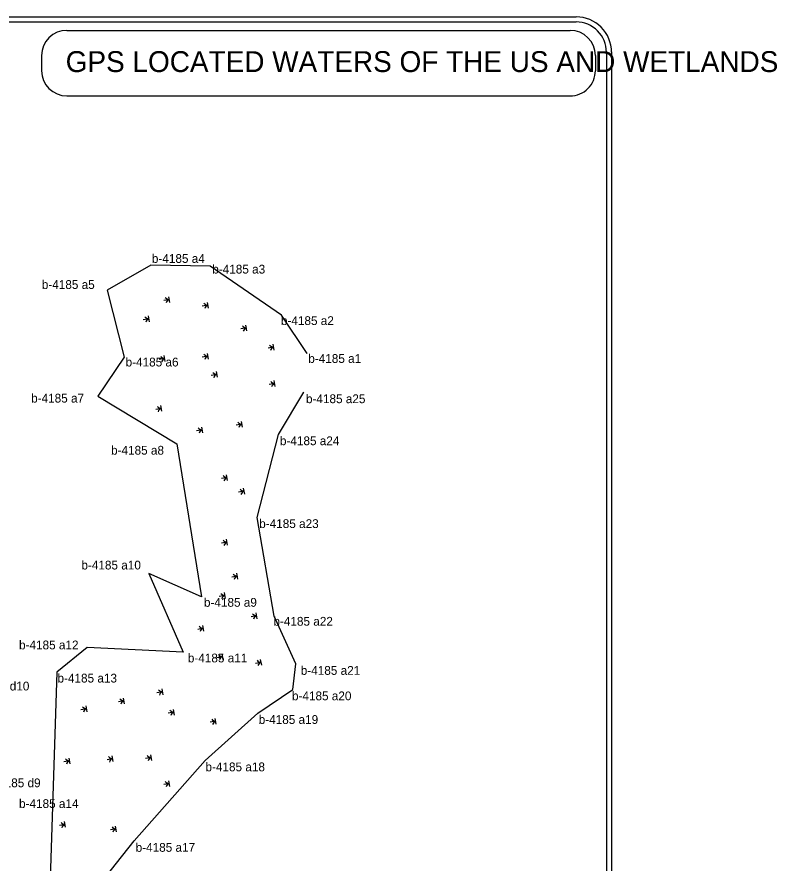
# Model space of a CAD drawing. Extents: x 2598976 to 2600165, y 728604 to 730243.
# Drawn here: x 2599517 to 2600165, y 729516 to 730238 of the extents above; entities that cross this region are included whole.
import ezdxf

# ---------------------------------------------------------------- set-up
doc = ezdxf.new("R2010")
doc.units = 0
for name, color, linetype in [('Old_Level_24', 7, 'Continuous'), ('Old_Level_3', 7, 'Continuous'), ('Old_Level_57', 7, 'Continuous'), ('Old_Level_63', 7, 'Continuous')]:
    doc.layers.add(name, color=color, linetype=linetype)

msp = doc.modelspace()

# ---------------------------------------------------------------- linework, layer by layer
at = {"layer": 'Old_Level_3'}
for p, q in [((2599631.03, 730026.43), (2599631.03, 730026.43)), ((2599681.7, 730025.47), (2599681.7, 730025.47)), ((2599593.82, 730004.86), (2599593.82, 730004.86)), ((2599742.64, 729983.6), (2599742.64, 729983.6)), ((2599764.34, 729950.8), (2599764.34, 729950.8)), ((2599608.29, 729947.7), (2599608.29, 729947.7)), ((2599585.75, 729914.54), (2599585.75, 729914.54)), ((2599761.65, 729918), (2599761.65, 729918)), ((2599739.87, 729881.74), (2599739.87, 729881.74)), ((2599653.16, 729873.76), (2599653.16, 729873.76)), ((2599721.7, 729811.02), (2599721.7, 729811.02)), ((2599629.44, 729763.19), (2599629.44, 729763.19)), ((2599674.31, 729743.3), (2599674.31, 729743.3)), ((2599736.31, 729726.61), (2599736.31, 729726.61)), ((2599576.74, 729699.88), (2599576.74, 729699.88)), ((2599658.53, 729696.04), (2599658.53, 729696.04)), ((2599754.67, 729686.08), (2599754.67, 729686.08)), ((2599550.79, 729678.88), (2599550.79, 729678.88)), ((2599752.22, 729664.15), (2599752.22, 729664.15)), ((2599722.5, 729643.95), (2599722.5, 729643.95)), ((2599677.31, 729603.47), (2599677.31, 729603.47)), ((2599616.95, 729534.95), (2599616.95, 729534.95))]:
    msp.add_line(p, q, dxfattribs=at)
at = {"layer": 'Old_Level_57'}
for p, q in [((2599646.85, 729996.92), (2599642.05, 729996.07)), ((2599647.28, 729994.46), (2599646.41, 729999.38)), ((2599680.17, 729989.62), (2599679.3, 729994.54)), ((2599679.73, 729992.08), (2599674.94, 729991.23)), ((2599629.43, 729980.47), (2599624.64, 729979.61)), ((2599629.87, 729978.01), (2599628.99, 729982.93)), ((2599712.62, 729972.73), (2599707.83, 729971.87)), ((2599713.06, 729970.26), (2599712.19, 729975.19)), ((2599736.28, 729953.81), (2599735.4, 729958.74)), ((2599680.17, 729946.07), (2599679.3, 729950.99)), ((2599735.84, 729956.27), (2599731.05, 729955.42)), ((2599642.98, 729946.6), (2599638.19, 729945.74)), ((2599643.41, 729944.14), (2599642.54, 729949.06)), ((2599679.73, 729948.53), (2599674.94, 729947.68)), ((2599687.91, 729930.59), (2599687.03, 729935.51)), ((2599687.47, 729933.05), (2599682.68, 729932.2)), ((2599736.81, 729925.31), (2599732.02, 729924.45)), ((2599737.24, 729922.85), (2599736.37, 729927.77)), ((2599640.51, 729901.56), (2599639.64, 729906.48)), ((2599640.07, 729904.02), (2599635.28, 729903.16)), ((2599709.19, 729888.01), (2599708.32, 729892.93)), ((2599674.9, 729885.63), (2599670.11, 729884.78)), ((2599675.34, 729883.17), (2599674.46, 729888.09)), ((2599708.75, 729890.47), (2599703.96, 729889.62)), ((2599696.18, 729844.98), (2599691.39, 729844.13)), ((2599696.62, 729842.52), (2599695.74, 729847.45)), ((2599711.13, 729830.91), (2599710.25, 729835.83)), ((2599710.69, 729833.37), (2599705.9, 729832.52)), ((2599696.62, 729787.36), (2599695.74, 729792.28)), ((2599696.18, 729789.82), (2599691.39, 729788.97)), ((2599705.32, 729758.33), (2599704.45, 729763.25)), ((2599704.88, 729760.79), (2599700.09, 729759.94)), ((2599694.24, 729744.34), (2599689.45, 729743.49)), ((2599694.68, 729741.88), (2599693.81, 729746.8)), ((2599721.33, 729726.92), (2599716.54, 729726.07)), ((2599721.77, 729724.46), (2599720.89, 729729.38)), ((2599676.3, 729713.81), (2599675.43, 729718.74)), ((2599675.86, 729716.28), (2599671.07, 729715.42)), ((2599692.31, 729692.08), (2599687.52, 729691.23)), ((2599692.75, 729689.62), (2599691.87, 729694.54)), ((2599725.64, 729684.78), (2599724.76, 729689.7)), ((2599725.2, 729687.24), (2599720.41, 729686.39)), ((2599641.04, 729662.08), (2599636.25, 729661.23)), ((2599641.48, 729659.62), (2599640.6, 729664.54)), ((2599608.15, 729654.34), (2599603.36, 729653.49)), ((2599608.59, 729651.88), (2599607.71, 729656.8)), ((2599576.23, 729647.57), (2599571.44, 729646.71)), ((2599576.67, 729645.1), (2599575.79, 729650.03)), ((2599651.15, 729642.2), (2599650.28, 729647.12)), ((2599650.71, 729644.66), (2599645.92, 729643.81)), ((2599686.94, 729634.46), (2599686.07, 729639.38)), ((2599686.51, 729636.92), (2599681.71, 729636.07)), ((2599561.72, 729603.05), (2599556.93, 729602.2)), ((2599562.16, 729600.59), (2599561.28, 729605.51)), ((2599598.48, 729604.99), (2599593.69, 729604.13)), ((2599598.92, 729602.52), (2599598.04, 729607.45)), ((2599631.37, 729605.95), (2599626.58, 729605.1)), ((2599631.81, 729603.49), (2599630.93, 729608.41)), ((2599646.85, 729583.7), (2599642.05, 729582.84)), ((2599647.28, 729581.23), (2599646.41, 729586.16)), ((2599557.85, 729548.86), (2599553.06, 729548)), ((2599558.29, 729546.4), (2599557.41, 729551.32)), ((2599601.82, 729542.52), (2599600.94, 729547.45)), ((2599601.38, 729544.99), (2599596.59, 729544.13))]:
    msp.add_line(p, q, dxfattribs=at)
msp.add_lwpolyline([(2599764.34, 729950.8), (2599742.64, 729983.6), (2599681.7, 730025.47), (2599631.03, 730026.43), (2599593.82, 730004.86), (2599608.29, 729947.7), (2599585.75, 729914.54), (2599653.16, 729873.76), (2599674.31, 729743.3), (2599629.44, 729763.19), (2599658.53, 729696.04), (2599576.74, 729699.88), (2599550.79, 729678.88), (2599545.29, 729502.48), (2599562.01, 729465.34), (2599616.95, 729534.95), (2599677.31, 729603.47), (2599722.5, 729643.95), (2599752.22, 729664.15), (2599754.67, 729686.08), (2599736.31, 729726.61), (2599721.7, 729811.02), (2599739.87, 729881.74), (2599761.65, 729918)], dxfattribs=at)
for centre, radius, start, end in [((2599647.31, 730002.05), 5.15, 220.90031, 264.24799), ((2599647.89, 729993.17), 3.87, 105.65345, 165.99432), ((2599680.2, 729997.22), 5.15, 220.90031, 264.24799), ((2599680.78, 729988.33), 3.87, 105.65345, 165.99432), ((2599629.9, 729985.6), 5.15, 220.90031, 264.24799), ((2599630.48, 729976.72), 3.87, 105.65345, 165.99432), ((2599713.09, 729977.86), 5.15, 220.90031, 264.24799), ((2599713.67, 729968.97), 3.87, 105.65345, 165.99432), ((2599736.31, 729961.41), 5.15, 220.90031, 264.24799), ((2599680.2, 729953.67), 5.15, 220.90031, 264.24799), ((2599736.89, 729952.52), 3.87, 105.65345, 165.99432), ((2599643.44, 729951.73), 5.15, 220.90031, 264.24799), ((2599644.02, 729942.85), 3.87, 105.65345, 165.99432), ((2599680.78, 729944.78), 3.87, 105.65345, 165.99432), ((2599687.94, 729938.18), 5.15, 220.90031, 264.24799), ((2599688.52, 729929.3), 3.87, 105.65345, 165.99432), ((2599737.27, 729930.44), 5.15, 220.90031, 264.24799), ((2599737.85, 729921.55), 3.87, 105.65345, 165.99432), ((2599640.54, 729909.15), 5.15, 220.90031, 264.24799), ((2599641.12, 729900.26), 3.87, 105.65345, 165.99432), ((2599709.22, 729895.6), 5.15, 220.90031, 264.24799), ((2599675.36, 729890.76), 5.15, 220.90031, 264.24799), ((2599675.95, 729881.88), 3.87, 105.65345, 165.99432), ((2599709.8, 729886.72), 3.87, 105.65345, 165.99432), ((2599696.65, 729850.12), 5.15, 220.90031, 264.24799), ((2599697.23, 729841.23), 3.87, 105.65345, 165.99432), ((2599711.16, 729838.51), 5.15, 220.90031, 264.24799), ((2599711.74, 729829.62), 3.87, 105.65345, 165.99432), ((2599696.65, 729794.96), 5.15, 220.90031, 264.24799), ((2599697.23, 729786.07), 3.87, 105.65345, 165.99432), ((2599705.35, 729765.93), 5.15, 220.90031, 264.24799), ((2599705.93, 729757.04), 3.87, 105.65345, 165.99432), ((2599694.71, 729749.47), 5.15, 220.90031, 264.24799), ((2599695.29, 729740.59), 3.87, 105.65345, 165.99432), ((2599721.8, 729732.05), 5.15, 220.90031, 264.24799), ((2599722.38, 729723.17), 3.87, 105.65345, 165.99432), ((2599676.33, 729721.41), 5.15, 220.90031, 264.24799), ((2599676.91, 729712.52), 3.87, 105.65345, 165.99432), ((2599692.78, 729697.22), 5.15, 220.90031, 264.24799), ((2599693.36, 729688.33), 3.87, 105.65345, 165.99432), ((2599725.67, 729692.38), 5.15, 220.90031, 264.24799), ((2599726.25, 729683.49), 3.87, 105.65345, 165.99432), ((2599641.51, 729667.22), 5.15, 220.90031, 264.24799), ((2599642.09, 729658.33), 3.87, 105.65345, 165.99432), ((2599608.62, 729659.47), 5.15, 220.90031, 264.24799), ((2599609.2, 729650.59), 3.87, 105.65345, 165.99432), ((2599576.7, 729652.7), 5.15, 220.90031, 264.24799), ((2599577.28, 729643.81), 3.87, 105.65345, 165.99432), ((2599651.18, 729649.8), 5.15, 220.90031, 264.24799), ((2599651.76, 729640.91), 3.87, 105.65345, 165.99432), ((2599686.97, 729642.06), 5.15, 220.90031, 264.24799), ((2599687.55, 729633.17), 3.87, 105.65345, 165.99432), ((2599562.19, 729608.18), 5.15, 220.90031, 264.24799), ((2599562.77, 729599.3), 3.87, 105.65345, 165.99432), ((2599598.95, 729610.12), 5.15, 220.90031, 264.24799), ((2599599.53, 729601.23), 3.87, 105.65345, 165.99432), ((2599631.83, 729611.09), 5.15, 220.90031, 264.24799), ((2599632.42, 729602.2), 3.87, 105.65345, 165.99432), ((2599647.31, 729588.83), 5.15, 220.90031, 264.24799), ((2599647.89, 729579.94), 3.87, 105.65345, 165.99432), ((2599558.32, 729553.99), 5.15, 220.90031, 264.24799), ((2599558.9, 729545.1), 3.87, 105.65345, 165.99432), ((2599601.85, 729550.12), 5.15, 220.90031, 264.24799), ((2599602.43, 729541.23), 3.87, 105.65345, 165.99432)]:
    msp.add_arc(centre, radius, start, end, dxfattribs=at)
at = {"layer": 'Old_Level_63'}
for p, q in [((2599010.7, 730238.21), (2599994, 730238.21)), ((2599010.7, 730238.21), (2599994, 730238.21)), ((2599010.7, 730238.21), (2599994, 730238.21)), ((2599011, 730233.91), (2599994, 730233.91)), ((2599011, 730233.91), (2599994, 730233.91)), ((2599011, 730233.91), (2599994, 730233.91)), ((2599559.38, 730226.75), (2599988.85, 730226.75)), ((2599537.87, 730205.24), (2599537.87, 730192.28)), ((2600010.36, 730205.24), (2600010.36, 730192.31)), ((2600019.84, 730208.54), (2600019.84, 728674.58)), ((2600019.84, 730208.54), (2600019.84, 728674.58)), ((2600019.84, 730208.54), (2600019.84, 728674.58)), ((2600024.14, 730208.54), (2600024.14, 728674.53)), ((2600024.14, 730208.54), (2600024.14, 728674.53)), ((2600024.14, 730208.54), (2600024.14, 728674.53)), ((2599559.38, 730170.78), (2599988.85, 730170.78))]:
    msp.add_line(p, q, dxfattribs=at)
for centre, major_axis, ratio, start_param, end_param in [((2599994, 730208.07), (-30.14, 0), 0.999993, 3.141591, 4.712389), ((2599994, 730208.07), (-30.14, 0), 0.999993, 3.141591, 4.712389), ((2599994, 730208.07), (-30.14, 0), 0.999993, 3.141591, 4.712389), ((2599994, 730208.07), (-25.83, 0), 0.999998, 3.141591, 4.712389), ((2599994, 730208.07), (-25.83, 0), 0.999998, 3.141591, 4.712389), ((2599994, 730208.07), (-25.83, 0), 0.999998, 3.141591, 4.712389), ((2599559.38, 730205.24), (0, -21.51), 0.999998, 3.141593, 4.712389), ((2599988.85, 730205.24), (0, 21.51), 0.999998, 4.712389, 6.283185), ((2599559.38, 730192.28), (0, -21.51), 0.999998, 4.712389, 6.283185), ((2599988.83, 730192.31), (0, 21.53), 0.999998, 3.141591, 4.712389)]:
    msp.add_ellipse(centre, major_axis=major_axis, ratio=ratio, start_param=start_param, end_param=end_param, dxfattribs=at)

# ---------------------------------------------------------------- texts
at = {"layer": 'Old_Level_24'}
for s, p in [('b-4185 a4', (2599631.96, 730028.23)), ('b-4185 a3', (2599683.47, 730019.14)), ('b-4185 a5', (2599538.03, 730006)), ('b-4185 a2', (2599742.05, 729975.18)), ('b-4185 a1', (2599765.39, 729942.85)), ('b-4185 a6', (2599609.54, 729939.82)), ('b-4185 a7', (2599528.94, 729909)), ('b-4185 a25', (2599763.43, 729908.49)), ('b-4185 a24', (2599741.21, 729872.62)), ('b-4185 a8', (2599597.12, 729864.54)), ('b-4185 a23', (2599723.54, 729801.89)), ('b-4185 a10', (2599571.82, 729766.52)), ('b-4185 a9', (2599676.37, 729734.69)), ('b-4185 a22', (2599735.66, 729718.52)), ('b-4185 a12', (2599518.61, 729698.32)), ('b-4185 a11', (2599662.64, 729687.2)), ('b-4185 a21', (2599758.99, 729676.59)), ('b-4185 a13', (2599551.44, 729670.02)), ('b-4185 d10', (2599476.68, 729663.24)), ('b-4185 a20', (2599751.49, 729654.86)), ('b-4185 a19', (2599723.11, 729634.66)), ('b-4185 a18', (2599677.69, 729594.24)), ('b-4185 d9', (2599491.86, 729580.63)), ('b-4185 a14', (2599518.61, 729562.91)), ('b-4185 a17', (2599618.1, 729525.53))]:
    msp.add_text(s, height=7.5, dxfattribs=at).set_placement(p)
at = {"layer": 'Old_Level_63'}
msp.add_text('GPS LOCATED WATERS OF THE US AND WETLANDS', height=17.831, dxfattribs=at).set_placement((2599558.41, 730191.14))

doc.saveas('drawing.dxf')
